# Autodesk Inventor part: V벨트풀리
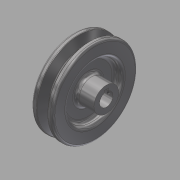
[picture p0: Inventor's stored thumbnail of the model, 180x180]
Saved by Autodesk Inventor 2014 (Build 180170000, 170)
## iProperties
Created: 2015-11
Part Number: V벨트풀리
Material: 강철, 탄소
Document SubType Name: Modeling
Designer: mduedu
Density: 7.87 g/cm^3
Appearance: 반광택
Mass: 430.041 g
Surface Area: 186.632 cm^2
Volume: 54.6431 cm^3
Author: mduedu
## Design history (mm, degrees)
sketch "스케치1"
  geometry: L1 (-9.5, 0)-(9.5, 0); L2 (0, 0)-(0, 37.7); L3 (-4.825, 37.7)-(-9.5, 37.7); L4 (-9.5, 37.7)-(-9.5, 0); L5 (0, 28.7)-(-2.074, 28.7); L6 (-2.074, 28.7)-(-4.825, 37.7); L7 (4.825, 37.7)-(9.5, 37.7); L8 (9.5, 37.7)-(9.5, 0); L9 (0, 28.7)-(2.074, 28.7); L10 (2.074, 28.7)-(4.825, 37.7); L11 (-9.5, 35)-(9.5, 35); 3 further points
  constraints: 22 end point, 7 point on line, 4 perpendicular, 3 symmetric about line, 1 coincident, 1 horizontal, 1 horizontal alignment, 1 midpoint, 1 vertical
  dimensions: "d0" = 19 distance of L1.start L1.end; "d2" = 75.4 diameter of L2.end L1 (derived); "d3" = 34 deg angle of L10 L6; "d4" = 6.3 distance between parallel lines of L11 L9; "d5" = 2.7 distance between parallel lines of L7 L11; "d6" = 8 distance of point (4, 35) point (-4, 35); "d7" = 70 diameter of L11 L1
revolve "회전1" sketch "스케치1" stored, may be unused: angle "d8" = 90 deg
sketch "스케치2"
  geometry: C1 r 24 at (0, 0); C2 r 11 at (0, 0); 1 further point
  constraints: 2 centre point, 2 coincident
  dimensions: "d9" = 48 diameter of C1; "d10" = 22 diameter of C2
extrude "돌출1" cut sketch "스케치2" distance "d11" = 6; taper "d12" = 0 deg
extrude "돌출3" join sketch "스케치2" distance "d37" = 10; taper "d38" = 0 deg
fillet "모깎기1" dims "d13" = 3
fillet "모깎기2" dims "d14" = 3
fillet "모깎기3" dims "d15" = 1, "d16" = 0.5, "d17" = 2
hole "구멍1" diameter "d20" = 12; stored, may be unused: countersink angle "d24" = 90 deg, drill point angle "d26" = 118 deg; dims "d21" = 6, "d22" = 4, "d23" = 2, "d25" = 8, "d39" = 10, "d40" = 10
sketch "스케치3"
  geometry: L1 (-2, 0)-(2, 0); L2 (2, 0)-(2, 7.8); L3 (2, 7.8)-(-2, 7.8); L4 (-2, 7.8)-(-2, 0); 2 further points
  constraints: 8 end point, 2 parallel, 1 coincident, 1 horizontal, 1 midpoint, 1 perpendicular
  dimensions: "d27" = 4 distance of L2.end L3.end; "d29" = 7.8 distance of L3.end L1.start
extrude "돌출2" cut sketch "스케치3" stored distance "d30" = 6; taper "d31" = 0 deg
chamfer "모따기1" distance "d32" = 0.5; stored, may be unused: second distance "d33" = 2, angle "d34" = 45 deg
node "작업 평면1"
sketch "스케치4"
  geometry: L1 (-19, 11)-(-19, -11) reference; 2 further points
  constraints: 1 horizontal alignment
  dimensions: "d41" = 25 distance from line of point (6, 0) L1
hole "구멍2" sketch "스케치4" at (6, 0) diameter "d42" = 2.459; stored, may be unused: countersink angle "d46" = 90 deg, drill point angle "d48" = 118 deg; dims "d43" = 6, "d44" = 4, "d45" = 2, "d47" = 8
node "솔리드1"
mirror "대칭1"
